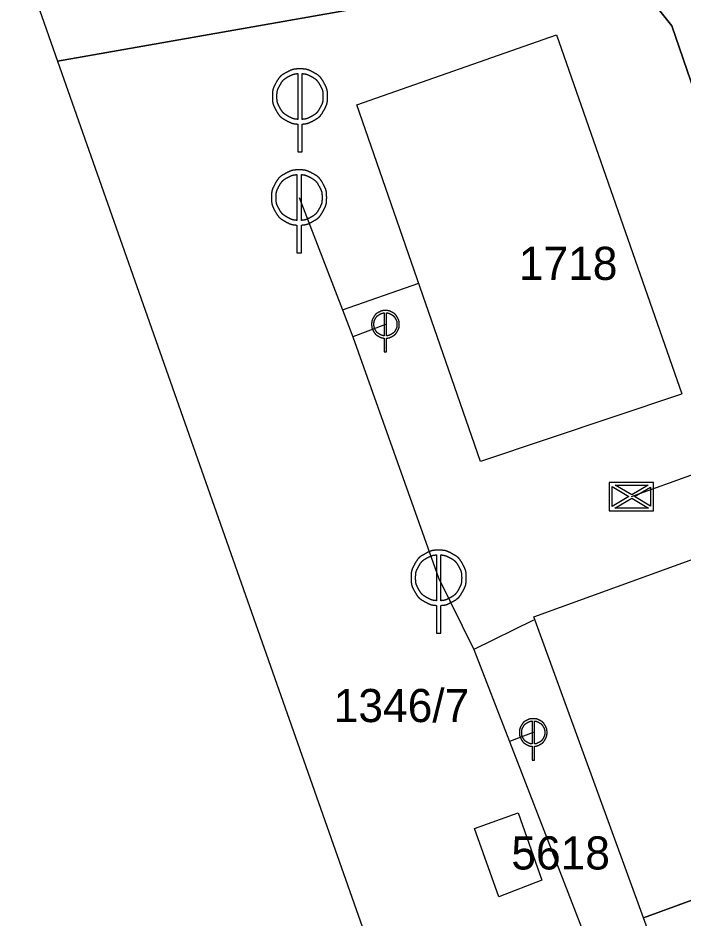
# Model space of a CAD drawing. Extents: x -562248 to -562040, y -1079385 to -1079027.
# Drawn here: x -562153.73 to -562123.63, y -1079190.52 to -1079149.79 of the extents above; entities that cross this region are included whole.
import ezdxf

# ---------------------------------------------------------------- set-up
doc = ezdxf.new("R2010")
doc.units = 0
for name, color, linetype in [('Default', 7, 'Continuous'), ('Dešťová vpusť', 7, 'Continuous'), ('Kanalizační přípojka', 7, 'Continuous'), ('Kanalizační stoka', 7, 'Continuous'), ('Kanalizační šachta', 7, 'Continuous'), ('Parcela-polygon', 7, 'Continuous'), ('Parcela-text', 7, 'Continuous')]:
    doc.layers.add(name, color=color, linetype=linetype)

msp = doc.modelspace()

# ---------------------------------------------------------------- linework, layer by layer
at = {"layer": 'Default'}
for points in [[(-562141.584, -1079152.251), (-562141.783, -1079152.358), (-562141.938, -1079152.512), (-562142.051, -1079152.712)], [(-562140.969, -1079152.09), (-562141.181, -1079152.09), (-562141.386, -1079152.143), (-562141.584, -1079152.251)], [(-562141.484, -1079152.434), (-562141.341, -1079152.357), (-562141.204, -1079152.313), (-562141.072, -1079152.302)], [(-562140.355, -1079152.251), (-562140.555, -1079152.143), (-562140.759, -1079152.09), (-562140.969, -1079152.09)], [(-562140.867, -1079152.302), (-562140.735, -1079152.313), (-562140.598, -1079152.357), (-562140.456, -1079152.434)], [(-562139.888, -1079152.712), (-562140, -1079152.512), (-562140.156, -1079152.358), (-562140.355, -1079152.251)], [(-562142.051, -1079152.712), (-562142.163, -1079152.912), (-562142.219, -1079153.122), (-562142.219, -1079153.34)], [(-562141.872, -1079152.818), (-562141.78, -1079152.652), (-562141.65, -1079152.523), (-562141.484, -1079152.434)], [(-562140.456, -1079152.434), (-562140.29, -1079152.523), (-562140.161, -1079152.652), (-562140.067, -1079152.818)], [(-562139.719, -1079153.34), (-562139.719, -1079153.122), (-562139.775, -1079152.912), (-562139.888, -1079152.712)], [(-562142.012, -1079153.34), (-562142.012, -1079153.159), (-562141.965, -1079152.985), (-562141.872, -1079152.818)], [(-562140.067, -1079152.818), (-562139.973, -1079152.985), (-562139.927, -1079153.159), (-562139.927, -1079153.34)], [(-562142.219, -1079153.34), (-562142.219, -1079153.556), (-562142.164, -1079153.764), (-562142.054, -1079153.962)], [(-562141.875, -1079153.857), (-562141.966, -1079153.693), (-562142.012, -1079153.52), (-562142.012, -1079153.34)], [(-562139.927, -1079153.34), (-562139.927, -1079153.52), (-562139.972, -1079153.693), (-562140.063, -1079153.857)], [(-562139.884, -1079153.962), (-562139.774, -1079153.764), (-562139.719, -1079153.556), (-562139.719, -1079153.34)], [(-562141.489, -1079154.241), (-562141.655, -1079154.149), (-562141.784, -1079154.022), (-562141.875, -1079153.857)], [(-562140.063, -1079153.857), (-562140.155, -1079154.022), (-562140.282, -1079154.149), (-562140.447, -1079154.241)], [(-562142.054, -1079153.962), (-562141.944, -1079154.161), (-562141.79, -1079154.315), (-562141.592, -1079154.424)], [(-562141.072, -1079154.375), (-562141.208, -1079154.365), (-562141.348, -1079154.32), (-562141.489, -1079154.241)], [(-562140.447, -1079154.241), (-562140.59, -1079154.32), (-562140.73, -1079154.365), (-562140.867, -1079154.375)], [(-562140.347, -1079154.424), (-562140.148, -1079154.315), (-562139.994, -1079154.161), (-562139.884, -1079153.962)], [(-562141.592, -1079154.424), (-562141.418, -1079154.521), (-562141.244, -1079154.576), (-562141.072, -1079154.587)], [(-562140.867, -1079154.587), (-562140.694, -1079154.576), (-562140.521, -1079154.521), (-562140.347, -1079154.424)], [(-562141.01, -1079156.66), (-562141.222, -1079156.66), (-562141.427, -1079156.714), (-562141.625, -1079156.821)], [(-562140.396, -1079156.821), (-562140.595, -1079156.714), (-562140.8, -1079156.66), (-562141.01, -1079156.66)], [(-562141.625, -1079156.821), (-562141.824, -1079156.929), (-562141.979, -1079157.082), (-562142.092, -1079157.283)], [(-562141.913, -1079157.389), (-562141.821, -1079157.222), (-562141.691, -1079157.094), (-562141.525, -1079157.004)], [(-562141.525, -1079157.004), (-562141.382, -1079156.928), (-562141.244, -1079156.884), (-562141.113, -1079156.872)], [(-562140.907, -1079156.872), (-562140.776, -1079156.884), (-562140.639, -1079156.928), (-562140.497, -1079157.004)], [(-562140.497, -1079157.004), (-562140.331, -1079157.094), (-562140.201, -1079157.222), (-562140.108, -1079157.389)], [(-562139.928, -1079157.283), (-562140.041, -1079157.082), (-562140.197, -1079156.929), (-562140.396, -1079156.821)], [(-562142.092, -1079157.283), (-562142.204, -1079157.483), (-562142.26, -1079157.692), (-562142.26, -1079157.91)], [(-562142.052, -1079157.91), (-562142.052, -1079157.729), (-562142.006, -1079157.556), (-562141.913, -1079157.389)], [(-562140.108, -1079157.389), (-562140.014, -1079157.556), (-562139.968, -1079157.729), (-562139.968, -1079157.91)], [(-562139.76, -1079157.91), (-562139.76, -1079157.692), (-562139.816, -1079157.483), (-562139.928, -1079157.283)], [(-562142.26, -1079157.91), (-562142.26, -1079158.126), (-562142.205, -1079158.334), (-562142.095, -1079158.533)], [(-562141.916, -1079158.428), (-562142.007, -1079158.263), (-562142.052, -1079158.091), (-562142.052, -1079157.91)], [(-562139.968, -1079157.91), (-562139.968, -1079158.091), (-562140.013, -1079158.263), (-562140.104, -1079158.428)], [(-562139.925, -1079158.533), (-562139.815, -1079158.334), (-562139.76, -1079158.126), (-562139.76, -1079157.91)], [(-562141.53, -1079158.811), (-562141.696, -1079158.72), (-562141.825, -1079158.592), (-562141.916, -1079158.428)], [(-562140.104, -1079158.428), (-562140.195, -1079158.592), (-562140.323, -1079158.72), (-562140.488, -1079158.811)], [(-562142.095, -1079158.533), (-562141.985, -1079158.731), (-562141.831, -1079158.885), (-562141.633, -1079158.994)], [(-562141.113, -1079158.945), (-562141.249, -1079158.935), (-562141.388, -1079158.891), (-562141.53, -1079158.811)], [(-562140.488, -1079158.811), (-562140.631, -1079158.891), (-562140.771, -1079158.935), (-562140.907, -1079158.945)], [(-562140.387, -1079158.994), (-562140.189, -1079158.885), (-562140.035, -1079158.731), (-562139.925, -1079158.533)], [(-562141.633, -1079158.994), (-562141.458, -1079159.092), (-562141.285, -1079159.146), (-562141.113, -1079159.158)], [(-562140.907, -1079159.158), (-562140.735, -1079159.146), (-562140.562, -1079159.092), (-562140.387, -1079158.994)], [(-562137.408, -1079163.106), (-562137.507, -1079163.159), (-562137.585, -1079163.236), (-562137.641, -1079163.336)], [(-562137.55, -1079163.389), (-562137.504, -1079163.306), (-562137.439, -1079163.241), (-562137.356, -1079163.196)], [(-562137.1, -1079163.025), (-562137.206, -1079163.025), (-562137.308, -1079163.052), (-562137.408, -1079163.106)], [(-562137.356, -1079163.196), (-562137.285, -1079163.158), (-562137.216, -1079163.136), (-562137.151, -1079163.13)], [(-562136.792, -1079163.106), (-562136.892, -1079163.052), (-562136.994, -1079163.025), (-562137.1, -1079163.025)], [(-562137.049, -1079163.13), (-562136.982, -1079163.136), (-562136.914, -1079163.158), (-562136.844, -1079163.196)], [(-562136.844, -1079163.196), (-562136.761, -1079163.241), (-562136.696, -1079163.306), (-562136.648, -1079163.389)], [(-562136.559, -1079163.336), (-562136.615, -1079163.236), (-562136.693, -1079163.159), (-562136.792, -1079163.106)], [(-562137.641, -1079163.336), (-562137.697, -1079163.436), (-562137.725, -1079163.541), (-562137.725, -1079163.65)], [(-562137.725, -1079163.65), (-562137.725, -1079163.757), (-562137.697, -1079163.861), (-562137.642, -1079163.96)], [(-562137.62, -1079163.65), (-562137.62, -1079163.559), (-562137.597, -1079163.472), (-562137.55, -1079163.389)], [(-562137.552, -1079163.908), (-562137.597, -1079163.825), (-562137.62, -1079163.74), (-562137.62, -1079163.65)], [(-562136.648, -1079163.389), (-562136.601, -1079163.472), (-562136.578, -1079163.559), (-562136.578, -1079163.65)], [(-562136.578, -1079163.65), (-562136.578, -1079163.74), (-562136.6, -1079163.825), (-562136.646, -1079163.908)], [(-562136.475, -1079163.65), (-562136.475, -1079163.541), (-562136.503, -1079163.436), (-562136.559, -1079163.336)], [(-562136.557, -1079163.96), (-562136.502, -1079163.861), (-562136.475, -1079163.757), (-562136.475, -1079163.65)], [(-562137.642, -1079163.96), (-562137.587, -1079164.059), (-562137.509, -1079164.137), (-562137.41, -1079164.192)], [(-562137.359, -1079164.099), (-562137.442, -1079164.054), (-562137.506, -1079163.99), (-562137.552, -1079163.908)], [(-562137.151, -1079164.168), (-562137.22, -1079164.163), (-562137.289, -1079164.14), (-562137.359, -1079164.099)], [(-562136.839, -1079164.099), (-562136.91, -1079164.14), (-562136.98, -1079164.163), (-562137.049, -1079164.168)], [(-562136.646, -1079163.908), (-562136.691, -1079163.99), (-562136.756, -1079164.054), (-562136.839, -1079164.099)], [(-562136.787, -1079164.192), (-562136.688, -1079164.137), (-562136.611, -1079164.059), (-562136.557, -1079163.96)], [(-562137.41, -1079164.192), (-562137.324, -1079164.241), (-562137.238, -1079164.268), (-562137.151, -1079164.273)], [(-562137.049, -1079164.273), (-562136.962, -1079164.268), (-562136.875, -1079164.241), (-562136.787, -1079164.192)], [(-562134.691, -1079173.87), (-562134.903, -1079173.87), (-562135.108, -1079173.924), (-562135.306, -1079174.032)], [(-562134.077, -1079174.032), (-562134.276, -1079173.924), (-562134.481, -1079173.87), (-562134.691, -1079173.87)], [(-562135.306, -1079174.032), (-562135.505, -1079174.139), (-562135.66, -1079174.293), (-562135.773, -1079174.493)], [(-562135.594, -1079174.599), (-562135.502, -1079174.432), (-562135.372, -1079174.304), (-562135.206, -1079174.215)], [(-562135.206, -1079174.215), (-562135.063, -1079174.138), (-562134.925, -1079174.094), (-562134.794, -1079174.083)], [(-562134.588, -1079174.083), (-562134.457, -1079174.094), (-562134.32, -1079174.138), (-562134.178, -1079174.215)], [(-562134.178, -1079174.215), (-562134.012, -1079174.304), (-562133.883, -1079174.432), (-562133.789, -1079174.599)], [(-562133.609, -1079174.493), (-562133.722, -1079174.293), (-562133.878, -1079174.139), (-562134.077, -1079174.032)], [(-562135.773, -1079174.493), (-562135.885, -1079174.693), (-562135.941, -1079174.902), (-562135.941, -1079175.12)], [(-562135.734, -1079175.12), (-562135.734, -1079174.94), (-562135.687, -1079174.766), (-562135.594, -1079174.599)], [(-562133.789, -1079174.599), (-562133.695, -1079174.766), (-562133.649, -1079174.94), (-562133.649, -1079175.12)], [(-562133.441, -1079175.12), (-562133.441, -1079174.902), (-562133.497, -1079174.693), (-562133.609, -1079174.493)], [(-562135.941, -1079175.12), (-562135.941, -1079175.337), (-562135.886, -1079175.544), (-562135.776, -1079175.743)], [(-562135.597, -1079175.638), (-562135.688, -1079175.474), (-562135.734, -1079175.301), (-562135.734, -1079175.12)], [(-562133.649, -1079175.12), (-562133.649, -1079175.301), (-562133.694, -1079175.474), (-562133.785, -1079175.638)], [(-562133.606, -1079175.743), (-562133.496, -1079175.544), (-562133.441, -1079175.337), (-562133.441, -1079175.12)], [(-562135.776, -1079175.743), (-562135.666, -1079175.942), (-562135.512, -1079176.095), (-562135.314, -1079176.204)], [(-562135.211, -1079176.021), (-562135.377, -1079175.93), (-562135.506, -1079175.802), (-562135.597, -1079175.638)], [(-562133.785, -1079175.638), (-562133.876, -1079175.802), (-562134.004, -1079175.93), (-562134.169, -1079176.021)], [(-562134.068, -1079176.204), (-562133.87, -1079176.095), (-562133.716, -1079175.942), (-562133.606, -1079175.743)], [(-562135.314, -1079176.204), (-562135.139, -1079176.302), (-562134.966, -1079176.357), (-562134.794, -1079176.368)], [(-562134.794, -1079176.156), (-562134.93, -1079176.146), (-562135.069, -1079176.101), (-562135.211, -1079176.021)], [(-562134.169, -1079176.021), (-562134.312, -1079176.101), (-562134.452, -1079176.146), (-562134.588, -1079176.156)], [(-562134.588, -1079176.368), (-562134.416, -1079176.357), (-562134.243, -1079176.302), (-562134.068, -1079176.204)], [(-562130.718, -1079181.576), (-562130.817, -1079181.629), (-562130.895, -1079181.706), (-562130.951, -1079181.806)], [(-562130.41, -1079181.495), (-562130.516, -1079181.495), (-562130.618, -1079181.522), (-562130.718, -1079181.576)], [(-562130.666, -1079181.666), (-562130.595, -1079181.628), (-562130.526, -1079181.606), (-562130.461, -1079181.6)], [(-562130.102, -1079181.576), (-562130.202, -1079181.522), (-562130.304, -1079181.495), (-562130.41, -1079181.495)], [(-562130.359, -1079181.6), (-562130.292, -1079181.606), (-562130.224, -1079181.628), (-562130.154, -1079181.666)], [(-562129.869, -1079181.806), (-562129.925, -1079181.706), (-562130.003, -1079181.629), (-562130.102, -1079181.576)], [(-562130.951, -1079181.806), (-562131.007, -1079181.906), (-562131.035, -1079182.011), (-562131.035, -1079182.12)], [(-562130.93, -1079182.12), (-562130.93, -1079182.029), (-562130.907, -1079181.942), (-562130.86, -1079181.859)], [(-562130.86, -1079181.859), (-562130.814, -1079181.776), (-562130.749, -1079181.711), (-562130.666, -1079181.666)], [(-562130.154, -1079181.666), (-562130.071, -1079181.711), (-562130.006, -1079181.776), (-562129.958, -1079181.859)], [(-562129.958, -1079181.859), (-562129.911, -1079181.942), (-562129.888, -1079182.029), (-562129.888, -1079182.12)], [(-562129.785, -1079182.12), (-562129.785, -1079182.011), (-562129.813, -1079181.906), (-562129.869, -1079181.806)], [(-562131.035, -1079182.12), (-562131.035, -1079182.227), (-562131.007, -1079182.331), (-562130.952, -1079182.43)], [(-562130.952, -1079182.43), (-562130.897, -1079182.529), (-562130.819, -1079182.607), (-562130.72, -1079182.662)], [(-562130.862, -1079182.378), (-562130.907, -1079182.295), (-562130.93, -1079182.21), (-562130.93, -1079182.12)], [(-562130.669, -1079182.569), (-562130.752, -1079182.524), (-562130.816, -1079182.46), (-562130.862, -1079182.378)], [(-562129.956, -1079182.378), (-562130.001, -1079182.46), (-562130.066, -1079182.524), (-562130.149, -1079182.569)], [(-562130.098, -1079182.662), (-562129.998, -1079182.607), (-562129.921, -1079182.529), (-562129.867, -1079182.43)], [(-562129.888, -1079182.12), (-562129.888, -1079182.21), (-562129.91, -1079182.295), (-562129.956, -1079182.378)], [(-562129.867, -1079182.43), (-562129.812, -1079182.331), (-562129.785, -1079182.227), (-562129.785, -1079182.12)], [(-562130.72, -1079182.662), (-562130.634, -1079182.711), (-562130.548, -1079182.738), (-562130.461, -1079182.743)], [(-562130.461, -1079182.638), (-562130.53, -1079182.633), (-562130.599, -1079182.61), (-562130.669, -1079182.569)], [(-562130.149, -1079182.569), (-562130.22, -1079182.61), (-562130.29, -1079182.633), (-562130.359, -1079182.638)], [(-562130.359, -1079182.743), (-562130.272, -1079182.738), (-562130.185, -1079182.711), (-562130.098, -1079182.662)]]:
    msp.add_open_spline(points, degree=2, dxfattribs=at)
at = {"layer": 'Dešťová vpusť'}
for points in [[(-562126.97, -1079172.093), (-562124.97, -1079172.093), (-562124.97, -1079170.805), (-562126.97, -1079170.805)], [(-562126.844, -1079171.896), (-562126.844, -1079170.993), (-562126.077, -1079171.444)], [(-562125.953, -1079171.372), (-562126.702, -1079170.93), (-562125.205, -1079170.93)], [(-562125.096, -1079171.878), (-562125.83, -1079171.444), (-562125.096, -1079171.012)], [(-562126.718, -1079171.968), (-562125.953, -1079171.517), (-562125.19, -1079171.968)]]:
    msp.add_lwpolyline(points, close=True, dxfattribs=at)
at = {"layer": 'Kanalizační přípojka'}
for points in [[(-562139.044, -1079162.99), (-562135.595, -1079161.78)], [(-562137.1, -1079163.65), (-562138.57, -1079164.22)], [(-562120.27, -1079169.41), (-562125.97, -1079171.45)], [(-562130.404, -1079177.038), (-562133.092, -1079178.37)], [(-562130.41, -1079182.12), (-562131.481, -1079182.534)]]:
    msp.add_lwpolyline(points, dxfattribs=at)
at = {"layer": 'Kanalizační stoka'}
msp.add_lwpolyline([(-562141.01, -1079157.91), (-562139.044, -1079162.99), (-562138.57, -1079164.22), (-562134.691, -1079175.12), (-562133.092, -1079178.37), (-562131.481, -1079182.534), (-562125.84, -1079197.1), (-562123.1, -1079204.19)], dxfattribs=at)
at = {"layer": 'Kanalizační šachta'}
for points in [[(-562141.072, -1079152.302), (-562141.072, -1079154.375)], [(-562140.867, -1079154.375), (-562140.867, -1079152.302)], [(-562141.072, -1079155.84), (-562140.867, -1079155.84), (-562140.867, -1079154.587)], [(-562141.072, -1079154.587), (-562141.072, -1079155.84)], [(-562141.113, -1079156.872), (-562141.113, -1079158.945)], [(-562140.907, -1079158.945), (-562140.907, -1079156.872)], [(-562141.113, -1079160.41), (-562140.907, -1079160.41), (-562140.907, -1079159.158)], [(-562141.113, -1079159.158), (-562141.113, -1079160.41)], [(-562137.151, -1079163.13), (-562137.151, -1079164.168)], [(-562137.049, -1079164.168), (-562137.049, -1079163.13)], [(-562137.151, -1079164.9), (-562137.049, -1079164.9), (-562137.049, -1079164.273)], [(-562137.151, -1079164.273), (-562137.151, -1079164.9)], [(-562134.794, -1079174.083), (-562134.794, -1079176.156)], [(-562134.588, -1079176.156), (-562134.588, -1079174.083)], [(-562134.794, -1079177.62), (-562134.588, -1079177.62), (-562134.588, -1079176.368)], [(-562134.794, -1079176.368), (-562134.794, -1079177.62)], [(-562130.461, -1079181.6), (-562130.461, -1079182.638)], [(-562130.359, -1079182.638), (-562130.359, -1079181.6)], [(-562130.461, -1079183.37), (-562130.359, -1079183.37), (-562130.359, -1079182.743)], [(-562130.461, -1079182.743), (-562130.461, -1079183.37)]]:
    msp.add_lwpolyline(points, dxfattribs=at)
at = {"layer": 'Parcela-polygon'}
for p, q in [((-562153.733, -1079146.647), (-562151.942, -1079151.733)), ((-562151.942, -1079151.733), (-562137.401, -1079193.038))]:
    msp.add_line(p, q, dxfattribs=at)
for points in [[(-562130.204, -1079213.482), (-562129.52, -1079213.24), (-562126.56, -1079212.06), (-562110.18, -1079204.89), (-562109.412, -1079204.67), (-562108.694, -1079204.319), (-562108.049, -1079203.848), (-562107.496, -1079203.271), (-562107.054, -1079202.606), (-562106.734, -1079201.874), (-562106.547, -1079201.097), (-562106.5, -1079200.3), (-562107.01, -1079197.84), (-562112.9, -1079182.58), (-562117.83, -1079168.5), (-562124.14, -1079150.14), (-562125.7, -1079148.16), (-562127.71, -1079147.6), (-562130.14, -1079147.9), (-562151.942, -1079151.733)], [(-562151.942, -1079151.733), (-562130.14, -1079147.9), (-562127.71, -1079147.6), (-562125.7, -1079148.16), (-562124.14, -1079150.14), (-562117.83, -1079168.5), (-562112.9, -1079182.58), (-562107.01, -1079197.84), (-562106.5, -1079200.3), (-562100.28, -1079214.7), (-562095.19, -1079227.16), (-562092.25, -1079234.14), (-562087.93, -1079243.96)], [(-562138.4, -1079153.71), (-562129.35, -1079150.55), (-562123.68, -1079166.8), (-562123.75, -1079166.82), (-562132.79, -1079169.85), (-562138.4, -1079153.71)], [(-562121.43, -1079173.64), (-562121.29, -1079173.59), (-562116.34, -1079187.19), (-562111.38, -1079200.8), (-562120.46, -1079204.1), (-562125.42, -1079190.5), (-562130.38, -1079176.88), (-562121.43, -1079173.64)], [(-562133.07, -1079186.46), (-562131.09, -1079185.76), (-562130.02, -1079188.8), (-562131.97, -1079189.55), (-562133.07, -1079186.46)]]:
    msp.add_lwpolyline(points, dxfattribs=at)
for points in [[(-562129.35, -1079150.55), (-562123.68, -1079166.8), (-562123.75, -1079166.82), (-562132.79, -1079169.85), (-562138.4, -1079153.71)], [(-562130.38, -1079176.88), (-562121.43, -1079173.64), (-562121.29, -1079173.59), (-562116.34, -1079187.19), (-562125.42, -1079190.5)], [(-562131.09, -1079185.76), (-562130.02, -1079188.8), (-562131.97, -1079189.55), (-562133.07, -1079186.46)], [(-562116.34, -1079187.19), (-562111.38, -1079200.8), (-562120.46, -1079204.1), (-562125.42, -1079190.5)]]:
    msp.add_lwpolyline(points, close=True, dxfattribs=at)

# ---------------------------------------------------------------- texts
at = {"layer": 'Parcela-text'}
for s, p in [('1718', (-562131.06, -1079161.64)), ('1346/7', (-562139.44, -1079181.65)), ('5618', (-562131.4, -1079188.32))]:
    msp.add_text(s, height=1.5, dxfattribs=at).set_placement(p)

doc.saveas('drawing.dxf')
